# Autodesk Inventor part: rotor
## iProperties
Created: 2006-01
Part Number: rotor
Document SubType Name: Modeling
Designer: Robbert
Manufacturer: Standard
Standards Organization: Custom
Author: Robbert
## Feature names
1. Extrusion1
2. Loft1
3. Circular Pattern1
4. Extrusion2
5. Fillet2
6. Extrusion3
7. Chamfer1
